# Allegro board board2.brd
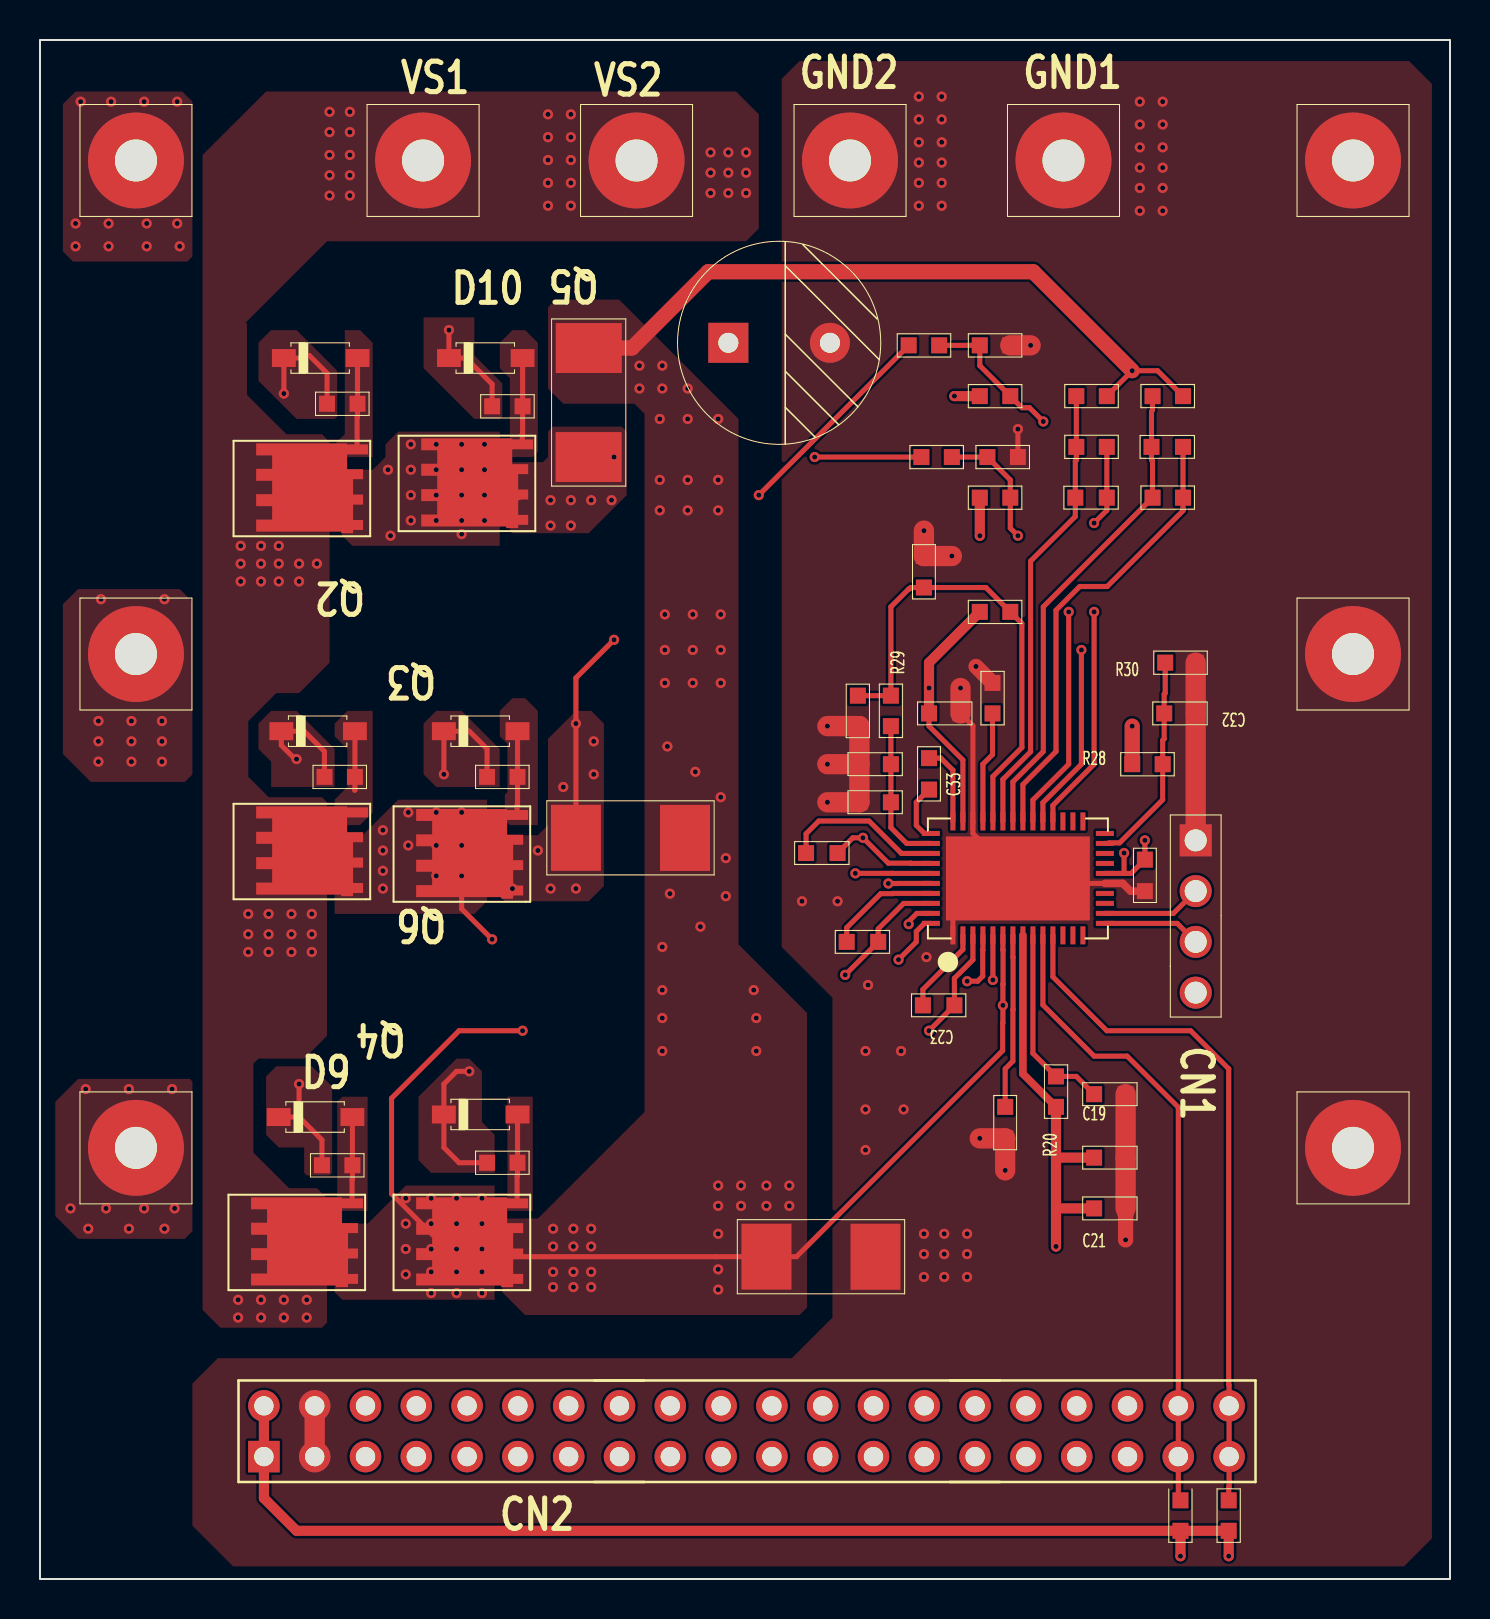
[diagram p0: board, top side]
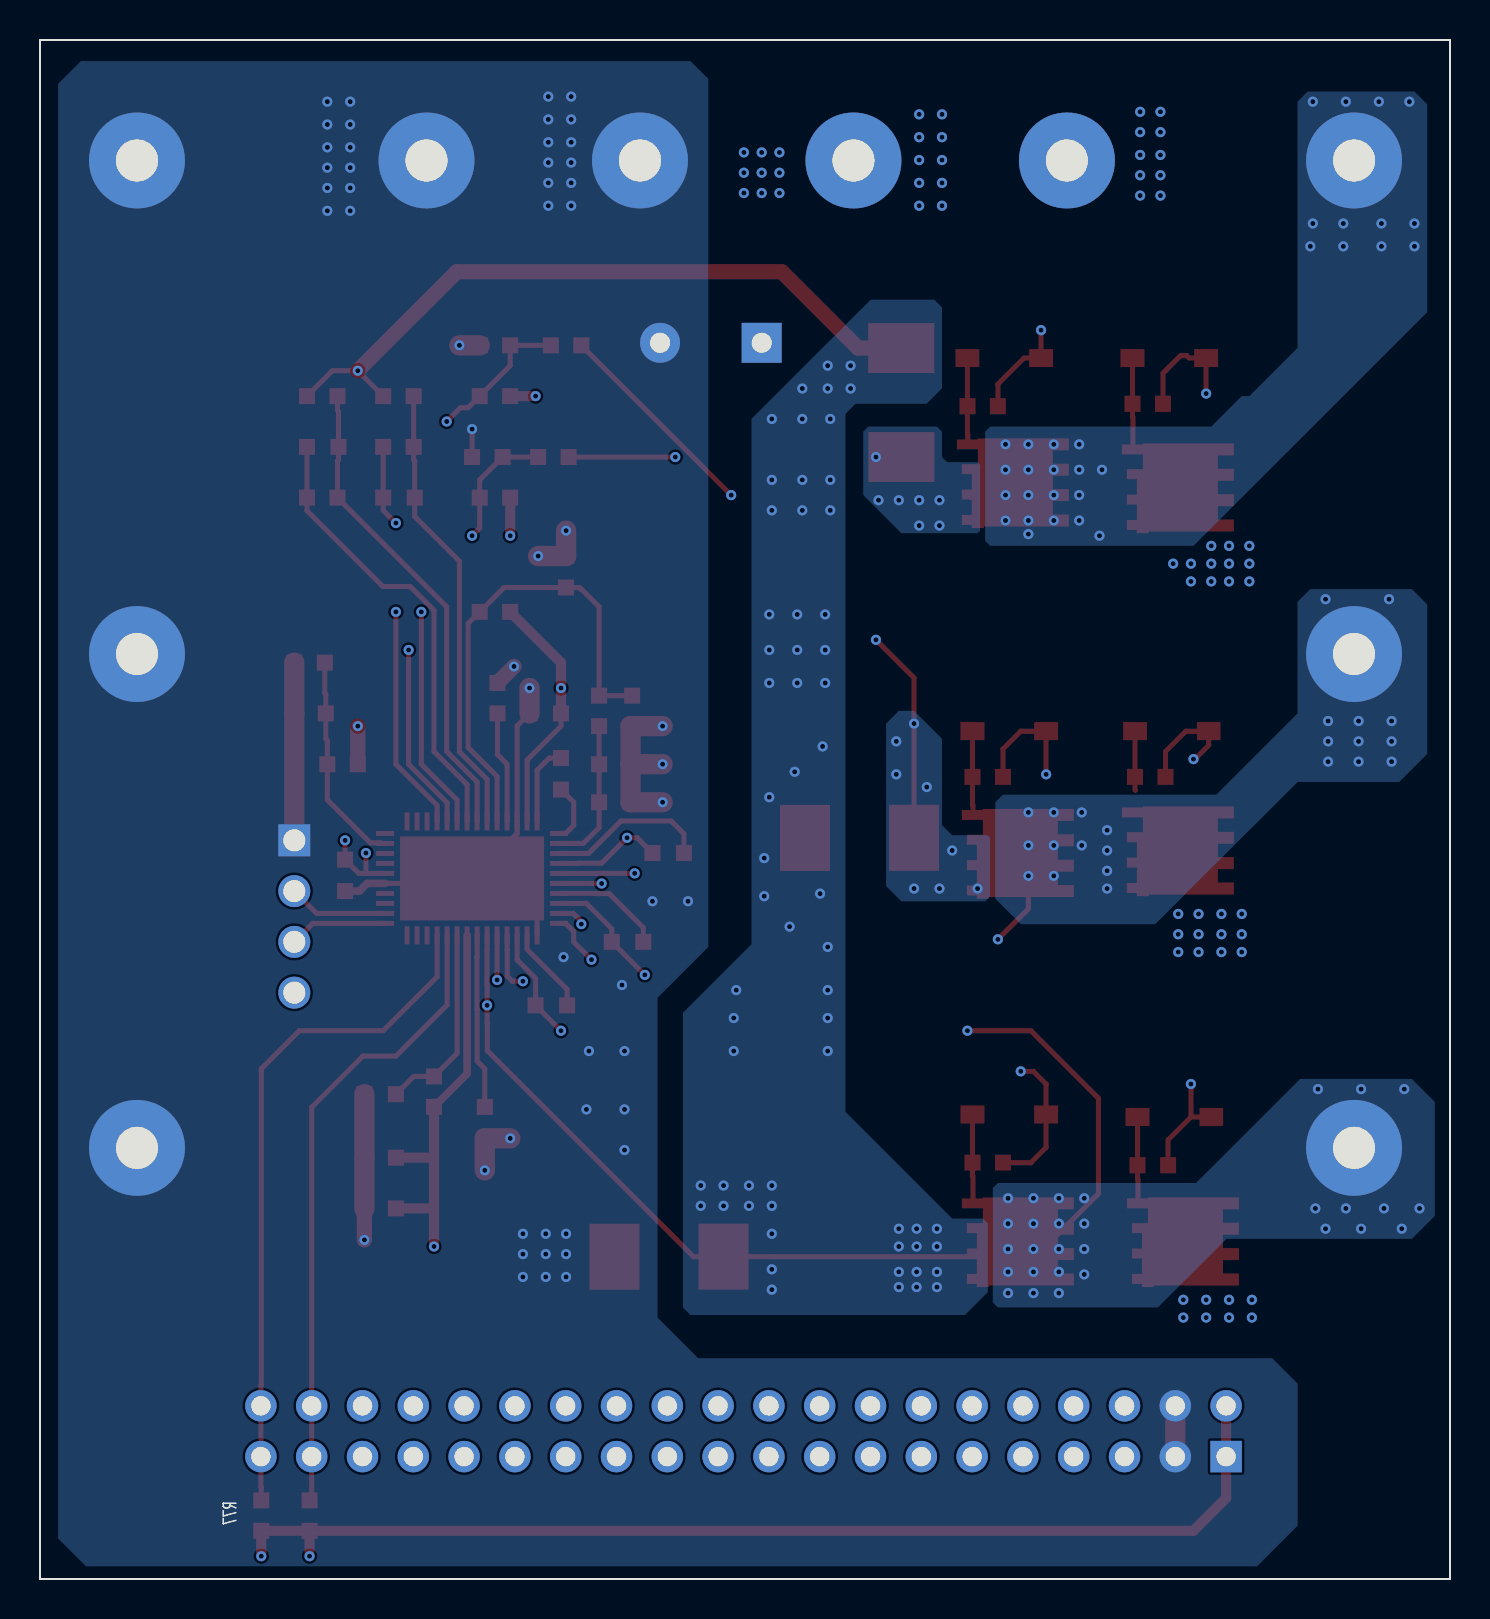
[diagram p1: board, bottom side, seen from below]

Outline 70.5 x 77 mm; copper layers: TOP, LAYER1, LAYER2, BOTTOM. Coordinates in mm from the lower left corner of the outline.
Outline path: rectangle 0,0 70.5,77

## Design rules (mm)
constraint set DEFAULT: min track width 0.127
net group N03788: nets N03788 N03879
net group N03886: nets N03886 N04171
net group IU: nets N05859 N05869 OP1- OP1O OP2- OP2O
net group OUT1: nets N03454
net group OUT2: nets N03434
net group OUT3: nets N03083

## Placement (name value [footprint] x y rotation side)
C19  0.1uF  [C0603]  52.7 24.26 0 top
C20  0.1uF  [C0603]  52.7 21.08 0 top
C21  10uF  [C0603]  52.7 18.54 0 top
C22  1uF  [C0603]  48.26 23.62 270 top
C23  0.47uF  [C0603]  45.72 28.7 180 top
C25  0.1uF  [C0603]  55.24 34.42 90 top
C30  0.47uF  [C0603]  41.91 31.88 180 top
C31  0.47uF  [C0603]  39.88 36.32 180 top
C32  0.1uF  [C0603]  57.78 43.31 180 top
C33  0.47uF  [C0603]  44.45 39.5 90 top
C34  10uF  [C0603]  42.55 38.86 180 top
C35  0.1uF  [C0603]  42.55 40.77 180 top
C36  0.1uF  [C0603]  44.45 43.31 0 top
C38  0.47uF  [C0603]  44.2 51.18 270 top
C45  0.01uF  [C0603]  53.34 54.1 180 top
C47  0.01uF  [C0603]  57.15 56.64 180 top
C48  330uF/35V  [CAP_ELECT_DIP_OD10_P5]  34.42 61.85 0 top
CN1  17.0017_4PIN_2.54mm  [CONN_DIP_4PIN_2_54MM]  57.78 36.96 270 top
CN2  17.0163_2X20_90D_female  [CONN_DIP_2X20PIN_2_54MM]  11.19 6.12 0 top
D7  200V;0.2A  [DIODES_SOD_123]  15.88 61.09 0 top
D8  200V;0.2A  [DIODES_SOD_123]  15.75 42.42 0 top
D9  200V;0.2A  [DIODES_SOD_123]  15.62 23.11 0 top
D10  200V;0.2A  [DIODES_SOD_123]  24.13 61.09 0 top
D11  200V;0.2A  [DIODES_SOD_123]  23.88 42.42 0 top
D12  200V;0.2A  [DIODES_SOD_123]  23.88 23.24 0 top
GND1  2.0mm_Male  [CONN_2_1MM_5_6MM]  51.18 70.97 0 top
GND2  2.0mm_Male  [CONN_2_1MM_5_6MM]  40.5 70.97 0 top
Q2  100V;90A  [MOS_TDSON8]  13.08 54.61 180 top
Q3  100V;90A  [MOS_TDSON8]  13.08 36.45 180 top
Q4  100V;90A  [MOS_TDSON8]  12.83 16.89 180 top
Q5  100V;90A  [MOS_TDSON8]  21.34 54.86 180 top
Q6  100V;90A  [MOS_TDSON8]  21.08 36.32 180 top
Q7  100V;90A  [MOS_TDSON8]  21.08 16.89 180 top
R20  10k  [R0603]  50.8 23.62 90 top
R28  120k  [R0603]  54.61 40.77 0 top
R29  100k  [R0603]  42.55 42.67 90 top
R30  10k  [R0603]  56.26 45.85 0 top
R31  15k  [R0603]  47.62 43.31 90 top
R33  NC  [R0603]  46.99 48.39 0 top
R36  NC  [R0603]  40.89 44.2 270 top
R43  47k  [R0603]  46.99 54.1 0 top
R44  47k  [R0603]  47.37 56.13 0 top
R45  1k  [R0603]  44.07 56.13 0 top
R47  1k  [R0603]  53.34 59.18 180 top
R51  51  [R0603]  14.35 58.8 0 top
R52  51  [R0603]  14.22 40.13 0 top
R53  51  [R0603]  14.1 20.7 0 top
R54  24k  [R0603]  53.34 56.64 180 top
R55  51  [R0603]  22.61 58.67 0 top
R56  51  [R0603]  22.35 40.13 0 top
R57  51  [R0603]  22.35 20.83 0 top
R58  47k  [R0603]  46.99 59.18 0 top
R59  47k  [R0603]  46.99 61.72 0 top
R60  0.002  [R2512]  27.43 56.13 90 top
R61  0.002  [R2512]  26.8 37.08 0 top
R62  1k  [R0603]  43.43 61.72 0 top
R64  1k  [R0603]  57.15 59.18 180 top
R65  0.005  [R2512]  36.32 16.13 0 top
R66  24k  [R0603]  57.15 54.1 180 top
R76  10k  [R0603]  57.02 3.94 270 top
R77  10k  [R0603]  59.44 3.94 270 top
U1  MPF66280  [QFN48_6X9MM]  48.9 35.05 90 top
UNK1  2.0mm_Male  [CONN_2_1MM_5_6MM]  4.8 70.97 0 top
UNK2  2.0mm_Male  [CONN_2_1MM_5_6MM]  65.65 70.97 0 top
UNK3  2.0mm_Male  [CONN_2_1MM_5_6MM]  4.8 46.28 0 top
UNK4  2.0mm_Male  [CONN_2_1MM_5_6MM]  65.65 46.28 0 top
UNK5  2.0mm_Male  [CONN_2_1MM_5_6MM]  4.8 21.57 0 top
UNK6  2.0mm_Male  [CONN_2_1MM_5_6MM]  65.65 21.57 0 top
VS1  2.0mm_Male  [CONN_2_1MM_5_6MM]  19.15 70.97 0 top
VS2  2.0mm_Male  [CONN_2_1MM_5_6MM]  29.83 70.97 0 top

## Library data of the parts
C19-C23 C30 C31 C33-C36 C45 C47 = CAP;16V;X7R;0603
C25 C32 C38 = CAP;10V;X7R;0603
C48 = ELECT CAP;330uF/35V;DIP10X12
CN1 = 17.0017_4PIN_2.54mm
CN2 = 17.0163_2X20_90D_female
D7-D12 = Diode;200V;0.2A;SOD-123
GND1 GND2 UNK1-UNK6 VS1 VS2 = 17.0025_2.0mm_Male
Q2-Q7 = NMOS;100V;7;42nc;90A;TDSON-8
R20 R28-R31 R33 R36 R43-R45 R47 R51-R59 R62 R64 R66 R76 R77 = RES;1%;0603
R60 R61 R65 = RES;1%;2512
U1 = IC;MPF66280_QFN48

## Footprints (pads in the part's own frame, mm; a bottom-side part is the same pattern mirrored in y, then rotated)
C0603
  rect 0.8x0.8 smd: 1(0,0) 2(1.575,0)
CAP_ELECT_DIP_OD10_P5
  rect 2x2 hole 1: 1(0,0)
  round 1.999 hole 1.001: 2(5.08,0)
CONN_2_1MM_5_6MM
  round 4.8 hole 2.1: 1(0,0)
CONN_DIP_2X20PIN_2_54MM
  rect 1.575x1.575 hole 0.965: 1(0,0)
  round 1.575 hole 0.965: 2(0,2.54) 3(2.54,0) 4(2.54,2.54) 5(5.08,0) 6(5.08,2.54) 7(7.62,0) 8(7.62,2.54) 9(10.16,0) 10(10.16,2.54) 11(12.7,0) 12(12.7,2.54) 13(15.24,0) 14(15.24,2.54) 15(17.78,0) 16(17.78,2.54) 17(20.32,0) 18(20.32,2.54) 19(22.86,0) 20(22.86,2.54) 21(25.4,0) 22(25.4,2.54) 23(27.94,0) 24(27.94,2.54) 25(30.48,0) 26(30.48,2.54) 27(33.02,0) 28(33.02,2.54) 29(35.56,0) 30(35.56,2.54) 31(38.1,0) 32(38.1,2.54) 33(40.64,0) 34(40.64,2.54) 35(43.18,0) 36(43.18,2.54) 37(45.72,0) 38(45.72,2.54) 39(48.26,0) 40(48.26,2.54)
CONN_DIP_4PIN_2_54MM
  rect 1.6x1.6 hole 1.1: 1(0,0)
  round 1.6 hole 1.1: 2(2.54,0) 3(5.08,0) 4(7.62,0)
DIODES_SOD_123
  rect 1.194x0.9 smd: 1(0,0) 2(-3.683,0)
MOS_TDSON8
  rect 1.1x0.5 smd: 1(-2.775,-1.905)
  custom 0.275x0.275 smd: 2(-2.525,0.685)
  custom 1.102x1.102 smd: 3(0,0)
QFN48_6X9MM
  rect 0.9x0.25 smd: 1(-2.85,3.25) 2(-2.85,2.75) 3(-2.85,2.25) 4(-2.85,1.75) 5(-2.85,1.25) 6(-2.85,0.75) 7(-2.85,0.25) 8(-2.85,-0.25) 9(-2.85,-0.75) 10(-2.85,-1.25) 11(-2.85,-1.75) 12(-2.85,-2.25) 13(-2.85,-2.75) 14(-2.85,-3.25) 25(2.85,-3.25) 26(2.85,-2.75) 27(2.85,-2.25) 28(2.85,-1.75) 29(2.85,-1.25) 30(2.85,-0.75) 31(2.85,-0.25) 32(2.85,0.25) 33(2.85,0.75) 34(2.85,1.25) 35(2.85,1.75) 36(2.85,2.25) 37(2.85,2.75) 38(2.85,3.25)
  rect 0.25x0.9 smd: 15(-2.25,-4.35) 16(-1.75,-4.35) 17(-1.25,-4.35) 18(-0.75,-4.35) 19(-0.25,-4.35) 20(0.25,-4.35) 21(0.75,-4.35) 22(1.25,-4.35) 23(1.75,-4.35) 24(2.25,-4.35) 39(2.25,4.35) 40(1.75,4.35) 41(1.25,4.35) 42(0.75,4.35) 43(0.25,4.35) 44(-0.25,4.35) 45(-0.75,4.35) 46(-1.25,4.35) 47(-1.75,4.35) 48(-2.25,4.35)
  rect 4.2x7.2 smd: 49(0,0)
R0603
  rect 0.8x0.8 smd: 1(0,0) 2(1.524,0)
R2512
  rect 2.5x3.302 smd: 1(0,0) 2(5.454,-0.006)

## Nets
GND: C19.2 C20.2 C21.2 C22.2 C25.1 C32.1 C34.2 C35.2 C36.2 C38.1 C48.2 CN1.1 CN2.3 CN2.4 GND1.1 GND2.1 R30.2 R31.2 R36.2 R44.2 R59.2 R65.2 U1.1 U1.19 U1.36 U1.49 UNK2.1 UNK4.1 UNK6.1
VIN: C36.1 C48.1 Q2.3 Q3.3 Q4.3 R28.1 R33.1 U1.37 VS1.1 VS2.1
+5: C20.1 C21.1 C25.2 CN1.4 CN2.1 CN2.2 R20.1 R43.1 R58.1 R76.2 R77.2 U1.8 U1.20
GHA: D7.2(\NN_PIN_2\) R51.1 U1.43
GHB: D8.2(\NN_PIN_2\) R52.1 U1.47
GHC: D9.2(\NN_PIN_2\) R53.1 U1.4
GLA: D10.2(\NN_PIN_2\) R55.1 U1.44
GLB: D11.2(\NN_PIN_2\) R56.1 U1.48
GLC: D12.2(\NN_PIN_2\) R57.1 U1.5
IU: Q5.2(\S\) R45.1 R60.1
IV: Q6.2(\S\) R61.1 R62.1
LSS: Q7.2(\S\) R47.1 R60.2 R61.2 R64.1 R65.1 U1.6
OP1-: C45.2 R47.2 R54.2 U1.33
OP1O: C45.1 R54.1 U1.28
OP2-: C47.2 R64.2 R66.2 U1.32
OP2O: C47.1 R66.1 U1.31
OUT1: C31.1 Q2.2(\S\) Q5.3 U1.42 UNK1.1
OUT2: C30.1 Q3.2(\S\) Q6.3 U1.46 UNK3.1
OUT3: C23.1 Q4.2(\S\) Q7.3 U1.3 UNK5.1
SCK: CN1.3 U1.15
SCL: CN2.37 CN2.38 R76.1 U1.10
SDA: CN2.39 CN2.40 R77.1 U1.11
SWD: CN1.2 U1.16
N00471: C32.2 R28.2 R30.1 U1.23
N02896: C19.1 R20.2 U1.9
N02916: C22.1 U1.7
N03083: C23.2 U1.2
N03434: C30.2 U1.45
N03454: C31.2 U1.41
N03788: C33.2 U1.38
N03879: C33.1 U1.39
N03886: C34.1 C35.1 R29.1 U1.40
N04171: C38.2 R29.2 R33.2 R36.1 U1.34
N04189: R31.1 U1.35
N05859: R58.2 R59.1 R62.2 U1.30
N05869: R43.2 R44.1 R45.2 U1.29
N16532: D7.1 Q2.1 R51.2
N16541: D10.1 Q5.1 R55.2
N16550: D11.1 Q6.1 R56.2
N16559: D12.1 Q7.1 R57.2
N16568: D8.1 Q3.1 R52.2
N16577: D9.1 Q4.1 R53.2

Pads without a net: CN2 5 6 7 8 9 10 11 12 13 14 15 16 17 18 19 20 21 22 23 24 25 26 27 28 29 30 31 32 33 34 35 36; U1 12 13 14 17 18 21 22 24 25 26 27

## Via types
v1: diameter 0.508, hole 0.254, TOP to BOTTOM, 310 vias

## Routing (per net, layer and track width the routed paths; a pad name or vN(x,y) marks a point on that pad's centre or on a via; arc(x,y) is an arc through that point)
GND: length 58.7
  TOP w0.127: 49.15,34.8 U1.49 47.62,35.05 45.64,33.07
  TOP w0.254: U1.49 46.64,37.3 U1.36 46.64,42.69 C36.2 ; U1.19 49.15,34.8 ; 45.64,33.07 U1.1 ; v1(48.9,57.53) R44.2
  TOP w0.381: U1.19 54.14,34.8 54.53,34.42 C25.1
  TOP w0.762: v1(46.8,45.66) R31.2 ; C21.2 v1(54.28,16.97)
  TOP w1.016: v1(39.37,38.86) C34.2 C35.2 ; C35.2 40.97,42.67 R36.2 v1(39.37,42.67) ; C35.2 v1(39.37,40.77) ; v1(44.2,52.45) C38.1 v1(45.59,51.18) ; R59.2 v1(49.53,61.72) ; C19.2 C20.2 C21.2 ; v1(46.99,22.05) C22.2 v1(48.26,20.45) ; v1(46.02,44.58) C36.2 ; CN2.3 CN2.4 ; CN1.1 C32.1 57.78,45.85
  vias: v1(38.1,33.91) v1(39.88,33.91) v1(41.27,26.42) v1(41.27,23.5) v1(41.27,21.46) v1(41.4,29.72) v1(43.05,26.42) v1(43.18,23.5) v1(43.94,74.17) v1(43.94,73.03) v1(43.94,71.88) v1(43.94,70.87) v1(43.94,69.85) v1(43.94,68.71) v1(44.2,17.27) v1(44.2,16.26) v1(44.2,15.11) v1(44.32,31.11) v1(45.09,74.17) v1(45.09,73.03) v1(45.09,71.88) v1(45.09,70.87) v1(45.09,69.85) v1(45.09,68.71) v1(45.21,17.27) v1(45.21,16.26) v1(45.21,15.11) v1(46.35,17.27) v1(46.35,16.26) v1(46.35,15.11) v1(54.99,73.91) v1(54.99,72.77) v1(54.99,71.63) v1(54.99,70.61) v1(54.99,69.6) v1(54.99,68.45) v1(56.13,73.91) v1(56.13,72.77) v1(56.13,71.63) v1(56.13,70.61) v1(56.13,69.6) v1(56.13,68.45)
VIN: length 59
  TOP w0.254: U1.37 46.14,40.98 44.45,42.67 C36.1
  TOP w0.508: C36.1 v1(44.45,44.58) 44.45,45.85 R33.1
  TOP w0.762: v1(54.61,42.67) R28.1
  LAYER1 w0.762: 44.32,47.75 40.89,51.18 40.89,55.37 C48.1 29.83,66.44 VS2.1 ; 44.32,47.75 44.45,47.62 v1(44.45,44.58) ; 44.32,47.75 49.53,47.75 v1(54.61,42.67)
  vias: v1(9.91,13.97) v1(9.91,13.08) v1(10.03,51.69) v1(10.03,50.8) v1(10.03,49.91) v1(10.41,33.27) v1(10.41,32.26) v1(10.41,31.37) v1(11.05,51.69) v1(11.05,50.8) v1(11.05,49.91) v1(11.05,13.97) v1(11.05,13.08) v1(11.43,33.27) v1(11.43,32.26) v1(11.43,31.37) v1(11.94,51.69) v1(11.94,50.8) v1(11.94,49.91) v1(12.19,13.97) v1(12.19,13.08) v1(12.57,33.27) v1(12.57,32.26) v1(12.57,31.37) v1(12.95,50.8) v1(12.95,49.91) v1(13.34,13.97) v1(13.34,13.08) v1(13.59,33.27) v1(13.59,32.26) v1(13.59,31.37) v1(13.84,50.8) v1(14.48,73.41) v1(14.48,72.39) v1(14.48,71.25) v1(14.48,70.23) v1(14.48,69.22) v1(15.49,73.41) v1(15.49,72.39) v1(15.49,71.25) v1(15.49,70.23) v1(15.49,69.22) v1(25.4,73.28) v1(25.4,72.14) v1(25.4,70.99) v1(25.4,69.85) v1(25.4,68.71) v1(26.54,73.28) v1(26.54,72.14) v1(26.54,70.99) v1(26.54,69.85) v1(26.54,68.71) v1(33.53,71.37) v1(33.53,70.36) v1(33.53,69.34) v1(34.42,71.37) v1(34.42,70.36) v1(34.42,69.34) v1(35.31,71.37) v1(35.31,70.36) v1(35.31,69.34)
+5: length 83.6
  TOP w0.254: v1(55.24,36.96) C25.2 54.56,35.3 54.2,35.3 ; v1(54.2,36.32) 54.2,35.3 ; 54.2,35.3 U1.20
  TOP w0.381: U1.8 49.15,25.28 R20.1
  TOP w0.508: v1(59.44,1.14) R77.2 R76.2 ; R76.2 12.83,2.41 11.19,4.05 CN2.1 CN2.2 ; R76.2 v1(57.02,1.14) ; C21.1 50.8,18.54 ; 50.8,18.54 50.8,21.08 ; 50.8,18.54 v1(50.8,16.64) ; R20.1 50.8,21.08 ; 50.8,21.08 C20.1 ; R43.1 v1(46.99,52.2) ; R58.1 v1(45.72,59.18)
GHA: length 50.9
  TOP w0.254: U1.43 42.63,35.3 42.63,35.31 v1(40.77,35.31) ; R51.1 14.35,60.33 13.46,61.21 13.17,61.21 13.04,61.09 D7.2 v1(12.19,59.31)
  LAYER2 w0.254: v1(40.77,35.31) 36.45,35.31 21.34,50.42 16.51,50.42 14.86,52.07 14.86,56.64 v1(12.19,59.31)
GHB: length 41.3
  TOP w0.254: v1(43.43,32.77) 43.43,32.9 43.84,33.3 U1.47 ; v1(12.83,41.02) 12.76,41.02 12.06,41.71 D8.2 13.21,42.42 14.22,41.4 R52.1
  LAYER2 w0.254: v1(43.43,32.77) 43.07,32.41 34.52,32.41 25.91,41.02 v1(12.83,41.02)
GHC: length 44
  TOP w0.254: D9.2 12.95,23.11 ; 12.95,23.11 v1(12.95,24.77) ; 12.95,23.11 14.1,21.97 R53.1 ; U1.4 47.14,31.48 47.14,31.47 47.14,30.16 46.88,29.91 v1(46.35,29.91)
  LAYER2 w0.254: v1(46.35,29.91) 43.75,29.91 42.55,28.7 16.89,28.7 v1(12.95,24.77)
GLA: length 60.2
  TOP w0.254: R55.1 22.61,59.78 21.3,61.09 D10.2 v1(20.45,62.48) ; v1(42.42,34.8) 42.93,34.8 42.93,34.8 U1.44
  LAYER2 w0.254: v1(20.45,62.48) 24.26,66.29 38.73,66.29 41.91,63.12 41.91,35.31 v1(42.42,34.8)
GLB: length 35.3
  TOP w0.254: U1.48 44.22,32.8 43.81,32.4 43.81,31.88 v1(42.93,30.99) ; R56.1 22.35,41.53 21.46,42.42 D11.2 v1(20.19,40.26)
  LAYER2 w0.254: v1(42.93,30.99) 33.53,30.99 25.15,39.37 21.08,39.37 v1(20.19,40.26)
GLC: length 37.8
  TOP w0.254: R57.1 20.95,20.83 20.19,21.59 D12.2 20.19,24.77 20.83,25.4 v1(21.46,25.4) ; U1.5 v1(47.64,29.97)
  LAYER2 w0.254: v1(47.64,29.97) 47.64,29.36 43.69,25.4 v1(21.46,25.4)
IU: length 16.8
  TOP w0.254: v1(28.7,56.13) R60.1 ; Q5.2 23.94,54.1 ; v1(38.73,56.13) R45.1
  LAYER2 w0.254: v1(38.73,56.13) v1(28.7,56.13)
  vias: v1(25.53,53.98) v1(25.53,52.7) v1(26.54,53.98) v1(26.54,52.7) v1(27.56,53.98) v1(28.57,53.98)
IV: length 31.5
  TOP w0.254: R62.1 v1(35.94,54.23) ; R61.1 v1(26.8,42.8) 26.8,45.09 v1(28.7,46.99)
  LAYER2 w0.254: v1(35.94,54.23) v1(28.7,46.99)
  vias: v1(23.62,34.54) v1(24.89,36.45) v1(25.53,34.54) v1(26.16,39.62) v1(26.8,34.54) v1(27.69,41.91) v1(27.69,40.26)
LSS: length 122.1
  TOP w0.254: R47.1 v1(54.61,60.45) 55.88,60.45 R64.1 ; U1.6 48.14,31.48 48.15,31.47 48.15,29.76 48.14,29.75 v1(48.14,28.7) 48.14,27.82 48.13,27.81 48.13,26.44 37.83,16.13 R65.1 33.8,16.13 33.8,16.13 23.69,16.13 Q7.2
  TOP w0.762: v1(54.61,60.45) 49.66,65.41 33.41,65.41 29.6,61.59 R60.2
  LAYER2 w0.254: v1(54.61,60.45) 55.24,61.09 59.44,61.09 60.33,60.2 60.33,28.32 58.8,26.8 50.05,26.8 v1(48.14,28.7)
  vias: v1(25.65,17.53) v1(25.65,16.64) v1(25.65,15.37) v1(25.65,14.61) v1(26.67,17.53) v1(26.67,16.64) v1(26.67,15.37) v1(26.67,14.61) v1(27.56,17.53) v1(27.56,16.64) v1(27.56,15.37) v1(27.56,14.61) v1(29.97,60.71) v1(29.97,59.56) v1(30.99,58.04) v1(30.99,54.99) v1(30.99,53.47) v1(31.11,60.71) v1(31.11,59.56) v1(31.11,31.62) v1(31.11,29.46) v1(31.11,28.07) v1(31.11,26.42) v1(31.24,48.26) v1(31.24,46.48) v1(31.24,44.83) v1(31.37,41.66) v1(31.5,34.29) v1(32.38,59.56) v1(32.38,58.04) v1(32.38,54.99) v1(32.38,53.47) v1(32.64,48.26) v1(32.64,46.48) v1(32.64,44.83) v1(32.77,40.39) v1(33.02,32.64) v1(33.91,58.04) v1(33.91,54.99) v1(33.91,53.47) v1(33.91,19.68) v1(33.91,18.67) v1(33.91,17.27) v1(33.91,15.49) v1(33.91,14.48) v1(34.04,48.26) v1(34.04,46.48) v1(34.04,44.83) v1(34.04,39.12) v1(34.29,36.07) v1(34.29,34.16) v1(35.05,19.68) v1(35.05,18.67) v1(35.69,29.46) v1(35.81,28.07) v1(35.81,26.42) v1(36.32,19.68) v1(36.32,18.67) v1(37.47,19.68) v1(37.47,18.67)
OP1-: length 22.8
  TOP w0.254: U1.33 48.14,40.01 49.53,41.39 49.53,50.93 51.77,53.16 C45.2 51.77,55.94 51.82,55.99 R54.2 R47.2
OP1O: length 19.9
  TOP w0.254: v1(52.7,52.83) 53.34,53.47 C45.1 R54.1 ; v1(52.7,48.39) 52.7,40.77 50.65,38.71 U1.28
  LAYER2 w0.254: v1(52.7,48.39) v1(52.7,52.83)
OP2-: length 24.2
  TOP w0.127: 55.63,58.48 55.58,58.43
  TOP w0.254: R64.2 55.63,58.48 ; U1.32 48.64,39.88 50.16,41.4 50.16,48.64 R66.2 55.63,55.94 55.58,55.99 C47.2 55.58,58.43
OP2O: length 22.9
  TOP w0.254: U1.31 49.15,39.75 50.8,41.4 50.8,48.47 51.99,49.66 53.36,49.66 57.15,53.45 R66.1 C47.1
OUT1: length 33.1
  TOP w0.127: Q5.3 21.08,54.86
  TOP w0.254: C31.1 40.64,37.08 v1(41.15,37.08) 42.42,35.81 43.55,35.81 43.56,35.8 U1.42 ; 20.29,53.81 Q5.3
  LAYER2 w0.254: v1(22.23,52.96) 22.23,52.28 22.27,52.28 36.83,37.72 40.51,37.72 v1(41.15,37.08)
  vias: v1(1.78,67.82) v1(1.78,66.67) v1(2.03,73.91) v1(3.43,67.82) v1(3.43,66.67) v1(3.56,73.91) v1(5.21,73.91) v1(5.33,67.82) v1(5.33,66.67) v1(6.86,73.91) v1(6.86,67.82) v1(6.99,66.67) v1(17.4,55.5) v1(17.53,52.2) v1(18.54,56.77) v1(18.54,55.5) v1(18.54,54.23) v1(18.54,52.96) v1(19.81,56.77) v1(19.81,55.5) v1(19.81,54.23) v1(19.81,52.96) v1(21.08,56.77) v1(21.08,55.5) v1(21.08,54.23) v1(21.08,52.96) v1(21.08,52.28) v1(22.23,56.77) v1(22.23,55.5) v1(22.23,54.23)
OUT2: length 30.8
  TOP w0.254: v1(21.08,36.7) Q6.3 v1(21.08,35.18) 21.08,33.53 v1(22.61,32) ; v1(40.26,30.23) C30.1 41.91,32.53 43.18,33.8 U1.46
  LAYER2 w0.254: v1(22.61,32) 24.38,30.23 v1(40.26,30.23) ; 19.77,37.72 19.18,37.72 18.92,37.97
  vias: v1(2.92,42.93) v1(2.92,41.91) v1(2.92,40.89) v1(3.05,49.02) v1(4.57,42.93) v1(4.57,41.91) v1(4.57,40.89) v1(6.1,42.93) v1(6.1,41.91) v1(6.1,40.89) v1(6.22,49.02) v1(17.14,37.47) v1(17.14,36.45) v1(17.14,35.43) v1(17.14,34.54) v1(18.41,38.35) v1(18.41,36.7) v1(19.81,38.35) v1(19.81,36.7) v1(19.81,35.18) v1(21.08,38.35)
OUT3: length 43.6
  TOP w0.254: 20.83,17.14 Q7.3 19.96,16.89 17.58,19.28 17.58,24.05 20.95,27.43 v1(24.13,27.43) ; U1.3 46.64,30.98 45.72,30.06 C23.1 v1(44.45,27.43)
  LAYER2 w0.254: v1(44.45,27.43) v1(24.13,27.43)
  vias: v1(1.52,18.54) v1(2.29,24.51) v1(2.41,17.53) v1(3.3,18.54) v1(4.45,24.51) v1(4.45,17.53) v1(5.21,18.54) v1(6.22,17.53) v1(6.6,24.51) v1(6.73,18.54) v1(18.29,19.05) v1(18.29,17.78) v1(18.29,16.51) v1(18.29,15.24) v1(19.56,19.05) v1(19.56,17.78) v1(19.56,16.51) v1(19.56,15.37) v1(19.56,14.31) v1(20.83,19.05) v1(20.83,17.78) v1(20.83,16.51) v1(20.83,15.37) v1(20.83,14.31) v1(22.1,19.05) v1(22.1,17.78) v1(22.1,16.51) v1(22.1,15.37) v1(22.1,14.31)
SCK: length 4.9
  TOP w0.254: 57.78,31.88 56.86,32.8 U1.15
SCL: length 32.1
  TOP w0.254: U1.10 50.15,28.72 52.7,26.16 54.36,26.16 56.91,23.6 CN2.38 CN2.37 56.91,4.05 R76.1
SDA: length 34.4
  TOP w0.254: U1.11 50.65,30.13 53.34,27.43 57.53,27.43 59.44,25.53 59.44,9.72 59.45,9.71 CN2.40 CN2.39 59.45,4.61 59.44,4.59 R77.1
SWD: length 5
  TOP w0.254: U1.16 56.67,33.3 CN1.2
N00471: length 10.7
  TOP w0.254: R30.1 56.26,44.32 56.21,44.27 C32.2 56.21,42.04 56.13,41.96 R28.2 56.13,38.99 53.98,36.83 53.47,36.83 53.47,36.8 U1.23
N02896: length 9.8
  TOP w0.254: U1.9 49.65,26.3 R20.2 51.82,25.15 C19.1
N02916: length 8.7
  TOP w0.254: U1.7 48.64,31.11 48.65,31.11 48.65,28.49 48.64,28.48 48.64,25.91 48.26,25.53 C22.1
N03083: length 4.3
  TOP w0.254: C23.2 44.15,29.5 46.14,31.5 U1.2
N03434: length 5.6
  TOP w0.254: U1.45 42.64,34.3 42.63,34.29 42.04,34.29 40.34,32.59 C30.2
N03454: length 8.1
  TOP w0.254: C31.2 38.3,37.29 38.94,37.92 41.45,37.92 43.07,36.3 U1.41
N03788: length 4
  TOP w0.254: C33.2 45.04,41.07 45.64,40.47 U1.38
N03879: length 3
  TOP w0.254: U1.39 44.22,37.3 43.81,37.71 43.81,38.86 C33.1
N03886: length 7.4
  TOP w0.254: R29.1 C35.1 C34.1 42.55,37.59 43.33,36.8 U1.40
N04171: length 24.3
  TOP w0.254: U1.34 47.64,40.15 49.09,41.6 49.09,47.81 R33.2 47.29,49.61 C38.2 43.54,49.61 43.47,49.53 43.43,49.53 42.55,48.64 R29.2 R36.1
N04189: length 5.6
  TOP w0.254: U1.35 47.14,40.77 47.62,41.25 R31.1
N05859: length 28.7
  TOP w0.254: U1.30 49.65,38.98 51.44,40.77 v1(51.44,48.39) ; R62.2 R59.1 46.99,60.71 R58.2 49.09,58.6 49.47,58.6 v1(50.16,57.91)
  LAYER2 w0.254: v1(51.44,48.39) 51.44,52.2 50.8,52.83 50.8,57.28 v1(50.16,57.91)
N05869: length 22.8
  TOP w0.254: v1(48.9,52.2) 48.51,52.58 R43.2 48.51,54.99 R44.1 R45.2 ; v1(52.07,46.48) 52.07,40.77 50.15,38.84 U1.29
  LAYER2 w0.254: v1(52.07,46.48) 52.07,47.03 48.9,50.21 v1(48.9,52.2)
N16532: length 4.3
  TOP w0.254: 15.86,56.77 15.86,58.13 15.88,58.15 R51.2 D7.1
N16541: length 4.3
  TOP w0.254: Q5.1 24.11,57.27 24.13,57.29 R55.2 D10.1
N16550: length 4.2
  TOP w0.254: D11.1 R56.2 23.88,38.75 23.86,38.73 Q6.1
N16559: length 4.5
  TOP w0.254: D12.1 R57.2 23.88,20.17 23.86,20.15 Q7.1
N16568: length 3
  TOP w0.254: D8.1 R52.2 15.75,39.48 15.73,39.46
N16577: length 4.3
  TOP w0.254: Q4.1 15.6,19.99 15.62,20.01 R53.2 D9.1

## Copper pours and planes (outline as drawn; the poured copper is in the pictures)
GND on TOP, BOTTOM, LAYER2: 37.08,75.06 37.08,31.62 39.62,29.08 39.62,13.08 37.59,11.05 8.89,11.05 7.62,9.78 7.62,2.67 9.65,0.64 68.2,0.64 69.6,2.03 69.6,74.8 68.45,75.95 37.97,75.95
VIN on TOP, LAYER1, LAYER2: 11.3,74.42 34.8,74.42 35.94,73.28 35.94,67.56 35.31,66.93 14.35,66.93 10.29,62.87 10.35,62.8 10.35,59.25 12.32,57.28 14.1,57.28 14.48,56.9 14.48,45.85 12.95,44.32 11.81,44.32 10.41,42.93 10.41,40.13 11.43,39.12 14.1,39.12 14.35,38.86 14.35,27.18 13.21,26.04 10.92,26.04 10.67,25.78 10.67,21.34 12.45,19.56 13.84,19.56 14.35,19.05 14.35,12.83 14.1,12.57 9.02,12.57 8.13,13.46 8.13,71.25
+5 on LAYER1: 37.08,75.06 37.08,31.62 39.62,29.08 39.62,13.08 37.59,11.05 8.89,11.05 7.62,9.78 7.62,2.67 9.65,0.64 68.2,0.64 69.6,2.03 69.6,74.8 68.45,75.95 37.97,75.95
GHA on TOP: 12.83,62.48 11.56,62.48 10.92,61.85 10.92,59.94 12.83,58.04 14.73,58.04 14.86,58.17 14.86,60.45
GHB on TOP: 11.56,39.62 14.73,39.62 14.73,41.53 12.83,43.43 11.56,43.43 10.92,42.8 10.92,41.53 11.56,40.89
GHC on TOP: 13.59,25.65 11.81,25.65 11.3,25.15 11.3,22.23 11.94,21.59 13.21,21.59 13.21,20.32 13.34,20.19 14.48,20.19 14.61,20.32 14.61,24.64
GLA on TOP: 21.72,61.21 21.72,63.12 19.18,63.12 19.18,60.58 21.72,58.04 22.99,58.04 23.11,58.17 23.11,59.82
GLB on TOP: 21.08,43.43 22.99,41.53 22.99,39.62 19.81,39.62 19.18,40.26 19.18,42.8 19.81,43.43
GLC on TOP: 21.46,26.04 20.83,26.04 18.92,24.13 18.92,20.95 19.56,20.32 22.73,20.32 22.73,22.23 22.1,22.86 22.1,25.4
IU on TOP, BOTTOM, LAYER1, LAYER2: 23.62,52.32 23.5,52.45 23.5,55.75 23.62,55.88 25.15,55.88 25.4,56.13 25.4,57.4 25.65,57.66 29.08,57.66 29.34,57.4 29.34,54.23 27.43,52.32
IV on TOP, BOTTOM, LAYER1, LAYER2: 22.99,34.16 22.99,37.08 23.11,37.21 24.89,37.21 25.4,37.72 25.4,42.04 26.8,43.43 27.56,43.43 28.19,42.8 28.19,34.67 27.43,33.91 23.24,33.91
LSS on TOP, BOTTOM, LAYER1, LAYER2: 25.4,63.63 25.4,59.56 26.16,58.8 29.72,58.8 30.23,58.29 30.23,23.37 24.89,18.03 23.37,18.03 23.11,17.78 23.11,14.35 24.26,13.21 37.97,13.21 38.35,13.59 38.35,28.32 34.92,31.75 34.92,58.04 28.96,64.01 25.78,64.01
OUT1 on TOP, LAYER1: 1.78,74.42 1.14,73.79 1.14,66.42 1.65,65.91 7.37,65.91 7.62,66.17 7.62,73.91 7.11,74.42
OUT1 on TOP, LAYER1, LAYER2: 15.24,55.5 16.64,55.5 17.27,56.13 17.27,56.77 17.91,57.4 22.99,57.4 22.99,51.69 15.62,51.69 15.11,52.2 15.11,55.37
OUT1 on BOTTOM: 22.99,51.69 12.83,51.69 1.14,63.37 1.14,73.79 1.78,74.42 7.11,74.42 7.62,73.91 7.62,61.59 10.03,59.18 10.41,59.18 11.94,57.66 22.99,57.66 23.24,57.4 23.24,51.94
OUT2 on TOP, LAYER1: 1.91,49.53 1.14,48.77 1.14,41.27 2.54,39.88 7.24,39.88 7.62,40.26 7.62,48.9 6.99,49.53
OUT2 on TOP, LAYER1, LAYER2: 14.73,33.27 14.73,37.08 16,37.08 17.91,38.99 22.35,38.99 22.35,33.91 21.72,33.27
OUT2 on BOTTOM: 1.14,48.77 1.91,49.53 6.99,49.53 7.62,48.9 7.62,43.31 11.68,39.24 22.35,39.24 22.73,38.86 22.73,34.04 21.46,32.77 14.73,32.77 7.62,39.88 2.54,39.88 1.14,41.27
OUT3 on TOP, LAYER1: 1.91,25.02 0.76,23.88 0.76,18.16 1.91,17.02 7.24,17.02 7.62,17.4 7.62,24.89 7.49,25.02
OUT3 on TOP, LAYER1, LAYER2: 14.99,17.78 16.38,17.78 18.29,19.68 22.73,19.68 22.73,13.97 15.11,13.97 14.73,14.35 14.73,17.53
OUT3 on BOTTOM: 0.76,23.88 1.91,25.02 7.49,25.02 12.7,19.81 22.61,19.81 22.86,19.56 22.86,13.84 22.61,13.59 14.61,13.59 11.18,17.02 1.91,17.02 0.76,18.16
N16532 on TOP: 16.64,56.13 16.64,61.85 16,62.48 15.24,62.48 15.24,57.28 14.73,56.77 14.73,56.13
N16541 on TOP: 23.62,56.13 24.64,56.13 24.89,56.39 24.89,61.85 24.26,62.48 23.62,62.48 22.99,61.85 22.99,60.58 23.5,60.07 23.5,56.26
N16550 on TOP: 24.89,37.72 24.89,43.43 24.26,44.07 23.62,44.07 22.99,43.43 22.99,42.16 23.37,41.78 23.37,39.37 23.24,39.24 23.24,37.97 23.5,37.72
N16559 on TOP: 23.37,18.41 24.64,18.41 24.64,24.13 23.37,24.13
N16568 on TOP: 14.73,38.35 14.73,38.99 15.37,39.62 15.37,41.53 14.73,42.16 14.73,42.8 15.37,43.43 16.64,43.43 16.64,38.35 16,37.72 15.37,37.72
N16577 on TOP: 16.38,24.13 16.38,18.41 14.99,18.41 14.86,18.54 14.86,23.88 15.11,24.13
